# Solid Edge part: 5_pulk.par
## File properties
Author: Romil
Template: iso part.par
Last saved by: Romil
Revision: 32
Application: Solid Edge
Accuracy: 0.990
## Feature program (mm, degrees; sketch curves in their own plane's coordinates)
sketch for "unnamed Protrusion 1" plane through (0, 0, 0) normal (1, 0, 0) x-axis (0, 1, 0)
  arc centre (0, 0) radius 2.35 from (2.181, 0.875) to (2.181, -0.875) cw
  arc centre (0, 0) radius 2.35 from (-0.875, 2.181) to (0.875, 2.181) cw
  arc centre (0, 0) radius 2.35 from (-2.181, -0.875) to (-2.181, 0.875) cw
extrude "unnamed Protrusion 1" add finite 38.8 symmetric
fillet "Round_4" radius 0.2  Radii2 = 0.2 mm
mirror "unnamed Mirror 1" of "Round_4" about plane through (0, 0, 0) normal (1, 0, 0)
fillet "unnamed Round 1"
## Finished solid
Body 1: solid body, 50 faces, 128 edges, 80 vertices.
  Faces by surface: cylinder 24, torus 16, plane 10
  Edges by curve: circle 48, line 48, intersection 32
Bounding box of the edges (mm; curved faces can reach further): 38.800 x 4.700 x 4.700, from (-19.4, -2.35, -2.35) to (19.4, 2.35, 2.35).
Cylindrical faces by radius (mm): R0.1 x4, R0.2 x16, R2.35 x4
Toroidal faces (ring radius, tube radius in mm): R0.3 r0.2 x8, R1.8 r0.55 x8
Planar faces by outward normal: +x 1, +y 2, +z 2, -x 1, -y 2, -z 2
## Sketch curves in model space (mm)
arc centre (0, -0.975, -0.975) radius 0.1 from (0, -0.975, -0.875) through (0, -0.9023, -0.9064) to (0, -0.875, -0.975)
line (0, -0.875, -0.975) -> (0, -0.875, -2.181)
arc centre (0, 0, 0) radius 2.35 from (0, 0.875, -2.181) through (0, 0, -2.35) to (0, -0.875, -2.181)
line (0, 0.875, -2.181) -> (0, 0.875, -0.975)
arc centre (0, 0.975, -0.975) radius 0.1 from (0, 0.875, -0.975) through (0, 0.9064, -0.9023) to (0, 0.975, -0.875)
line (0, 0.975, -0.875) -> (0, 2.181, -0.875)
arc centre (0, 0, 0) radius 2.35 from (0, 2.181, 0.875) through (0, 2.35, 0) to (0, 2.181, -0.875)
line (0, 2.181, 0.875) -> (0, 0.975, 0.875)
arc centre (0, 0.975, 0.975) radius 0.1 from (0, 0.975, 0.875) through (0, 0.9023, 0.9064) to (0, 0.875, 0.975)
line (0, 0.875, 0.975) -> (0, 0.875, 2.181)
arc centre (0, 0, 0) radius 2.35 from (0, -0.875, 2.181) through (0, 0, 2.35) to (0, 0.875, 2.181)
line (0, -0.875, 2.181) -> (0, -0.875, 0.975)
arc centre (0, -0.975, 0.975) radius 0.1 from (0, -0.875, 0.975) through (0, -0.9064, 0.9023) to (0, -0.975, 0.875)
line (0, -0.975, 0.875) -> (0, -2.181, 0.875)
arc centre (0, 0, 0) radius 2.35 from (0, -2.181, -0.875) through (0, -2.35, 0) to (0, -2.181, 0.875)
line (0, -2.181, -0.875) -> (0, -0.975, -0.875)
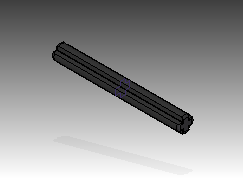
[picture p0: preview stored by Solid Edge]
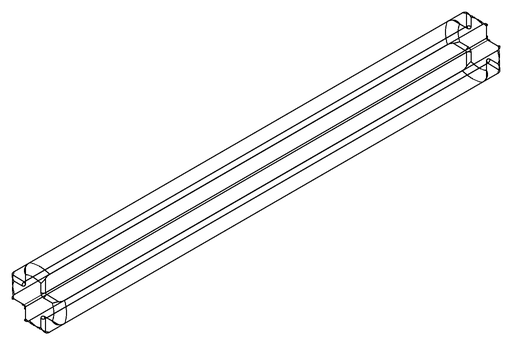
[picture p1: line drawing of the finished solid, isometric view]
